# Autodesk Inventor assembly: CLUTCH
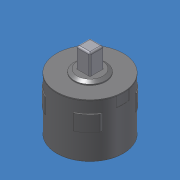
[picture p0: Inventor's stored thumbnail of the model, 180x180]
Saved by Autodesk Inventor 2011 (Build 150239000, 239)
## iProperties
Created: 2007-08
Part Number: CLUTCH
Document SubType Name: Assembly
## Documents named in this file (3)
- C:\Data Folder\VEX 2011\Inventor Datasets\Unit 15\Components\CLUTCH.iam
- C:\Data Folder\VEX 2011\Inventor Datasets\Unit 15\Components\Clutch Body.ipt
- C:\Data Folder\VEX 2011\Inventor Datasets\Unit 15\Components\Clutch Axle.ipt
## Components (2 placed, 2 different names)
1. Clutch Body:1 — Mate:1, Mate:2, Mate:3
2. Clutch Axle:1 — Mate:1, Mate:2, Mate:3
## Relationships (3: Mate 3)
- Mate:1: Clutch Body:1 ↔ Clutch Axle:1
- Mate:2: Clutch Body:1 ↔ Clutch Axle:1
- Mate:3: Clutch Body:1 ↔ Clutch Axle:1
